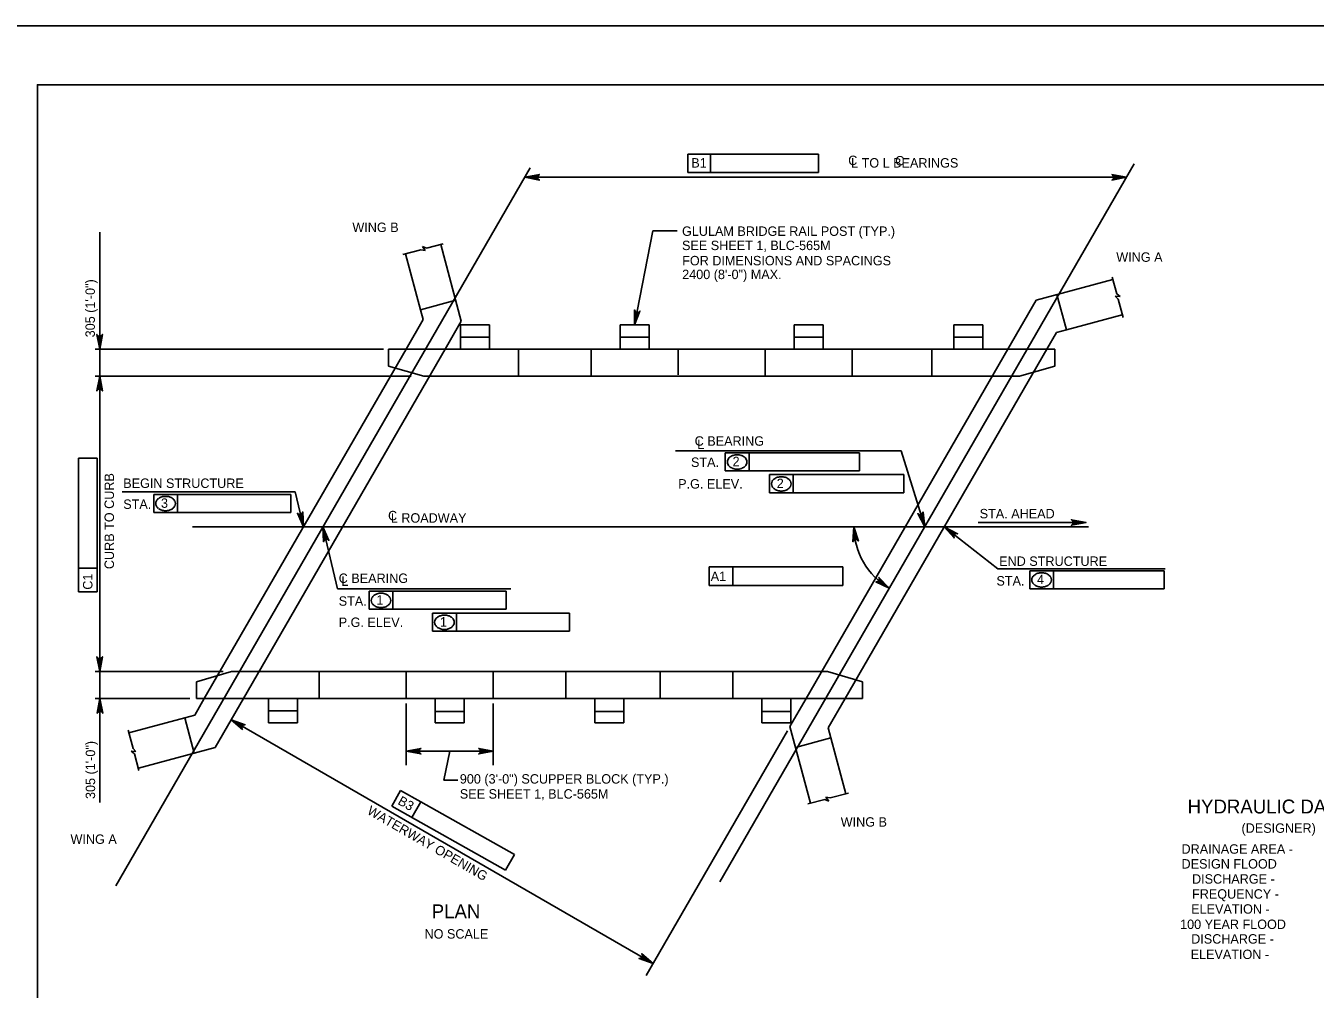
# Model space of a CAD drawing. Extents: x -8 to 75, y -110 to 0.
# Drawn here: x 1.6 to 18.01, y -12.26 to 0 of the extents above; entities that cross this region are included whole.
import ezdxf

# ---------------------------------------------------------------- set-up
doc = ezdxf.new("R2010")
doc.units = 0
for name, color, linetype in [('1', 7, 'Continuous'), ('2', 7, 'Continuous'), ('3', 7, 'Continuous'), ('4', 7, 'Continuous'), ('63', 7, 'Continuous')]:
    doc.layers.add(name, color=color, linetype=linetype)

msp = doc.modelspace()

# ---------------------------------------------------------------- linework, layer by layer
at = {"layer": '1'}
msp.add_lwpolyline([(1.75, -21.25), (33.25, -21.25), (33.25, -0.75), (1.75, -0.75)], close=True, dxfattribs=at)
at = {"layer": '2'}
for p, q in [((7.144, -3.757), (6.882, -2.781)), ((6.623, -3.613), (6.432, -2.902)), ((14.457, -3.491), (15.433, -3.229)), ((14.842, -3.869), (14.721, -3.42)), ((6.623, -3.613), (7.073, -3.493)), ((14.457, -3.491), (14.097, -4.113)), ((6.441, -4.113), (6.657, -3.739)), ((6.657, -3.739), (6.623, -3.613)), ((7.144, -3.757), (6.938, -4.113)), ((14.842, -3.869), (15.553, -3.679)), ((7.502, -3.806), (7.133, -3.806)), ((7.133, -3.806), (7.133, -4.113)), ((7.502, -3.806), (7.502, -4.113)), ((9.532, -3.806), (9.163, -3.806)), ((9.163, -3.806), (9.163, -4.113)), ((9.532, -3.806), (9.532, -4.113)), ((11.379, -3.806), (11.748, -3.806)), ((11.379, -3.806), (11.379, -4.113)), ((11.748, -3.806), (11.748, -4.113)), ((13.409, -3.806), (13.778, -3.806)), ((13.409, -3.806), (13.409, -4.113)), ((13.778, -3.806), (13.778, -4.113)), ((14.594, -4.113), (14.716, -3.903)), ((14.716, -3.903), (14.842, -3.869)), ((3.873, -8.56), (6.441, -4.113)), ((4.371, -8.56), (6.938, -4.113)), ((6.218, -4.113), (14.693, -4.113)), ((6.218, -4.329), (6.218, -4.113)), ((11.53, -8.56), (14.097, -4.113)), ((12.027, -8.56), (14.594, -4.113)), ((14.693, -4.329), (14.693, -4.113)), ((6.665, -4.459), (6.218, -4.329)), ((14.246, -4.459), (14.693, -4.329)), ((14.246, -4.459), (6.665, -4.459)), ((4.222, -8.214), (3.775, -8.345)), ((3.775, -8.345), (3.775, -8.56)), ((11.803, -8.214), (4.222, -8.214)), ((11.803, -8.214), (12.25, -8.345)), ((12.25, -8.345), (12.25, -8.56)), ((3.752, -8.771), (3.873, -8.56)), ((3.775, -8.56), (12.25, -8.56)), ((4.371, -8.56), (4.011, -9.183)), ((4.69, -8.868), (4.69, -8.56)), ((5.059, -8.868), (5.059, -8.56)), ((6.812, -8.868), (6.812, -8.56)), ((7.181, -8.868), (7.181, -8.56)), ((8.843, -8.868), (8.843, -8.56)), ((9.212, -8.868), (9.212, -8.56)), ((10.966, -8.868), (10.966, -8.56)), ((11.324, -8.916), (11.53, -8.56)), ((11.335, -8.868), (11.335, -8.56)), ((11.811, -8.934), (12.027, -8.56)), ((3.626, -8.804), (2.914, -8.995)), ((3.752, -8.771), (3.626, -8.804)), ((3.626, -8.804), (3.746, -9.254)), ((7.181, -8.725), (6.812, -8.725)), ((8.843, -8.725), (9.212, -8.725)), ((10.966, -8.725), (11.335, -8.725)), ((5.059, -8.868), (4.69, -8.868)), ((7.181, -8.868), (6.812, -8.868)), ((8.843, -8.868), (9.212, -8.868)), ((10.966, -8.868), (11.335, -8.868)), ((11.324, -8.916), (11.586, -9.893)), ((11.811, -8.934), (11.845, -9.06)), ((4.011, -9.183), (3.035, -9.445)), ((11.845, -9.06), (11.395, -9.181)), ((11.845, -9.06), (12.035, -9.772))]:
    msp.add_line(p, q, dxfattribs=at)
at = {"layer": '3'}
for p, q in [((10.433, -10.89), (15.706, -1.757)), ((2.747, -10.942), (8.02, -1.808)), ((6.7, -2.83), (6.914, -2.773)), ((6.398, -2.911), (6.631, -2.849)), ((6.684, -2.86), (6.631, -2.849)), ((6.65, -2.808), (6.684, -2.86)), ((6.7, -2.83), (6.65, -2.808)), ((15.482, -3.411), (15.424, -3.197)), ((15.463, -3.44), (15.5, -3.48)), ((15.525, -3.443), (15.463, -3.44)), ((15.482, -3.411), (15.525, -3.443)), ((15.563, -3.713), (15.5, -3.48)), ((7.502, -3.96), (7.133, -3.96)), ((9.532, -3.96), (9.163, -3.96)), ((11.379, -3.96), (11.748, -3.96)), ((13.409, -3.96), (13.778, -3.96)), ((7.871, -4.459), (7.871, -4.113)), ((8.794, -4.459), (8.794, -4.113)), ((9.902, -4.113), (9.902, -4.443)), ((11.009, -4.113), (11.009, -4.459)), ((12.117, -4.113), (12.117, -4.459)), ((13.132, -4.113), (13.132, -4.459)), ((5.335, -8.214), (5.335, -8.56)), ((6.443, -8.214), (6.443, -8.56)), ((7.551, -8.214), (7.551, -8.56)), ((8.474, -8.214), (8.474, -8.56)), ((9.674, -8.214), (9.674, -8.56)), ((10.597, -8.214), (10.597, -8.56)), ((5.059, -8.714), (4.69, -8.714)), ((2.905, -8.96), (2.968, -9.194)), ((2.986, -9.263), (2.942, -9.23)), ((2.942, -9.23), (3.005, -9.234)), ((3.005, -9.234), (2.968, -9.194)), ((2.986, -9.263), (3.043, -9.476)), ((11.818, -9.865), (11.783, -9.813)), ((11.783, -9.813), (11.837, -9.825)), ((12.07, -9.763), (11.837, -9.825)), ((11.767, -9.844), (11.554, -9.901)), ((11.767, -9.844), (11.818, -9.865))]:
    msp.add_line(p, q, dxfattribs=at)
at = {"layer": '4'}
for p, q in [((10.027, -1.634), (10.316, -1.634)), ((10.027, -1.865), (10.027, -1.634)), ((10.316, -1.865), (10.316, -1.634)), ((10.316, -1.634), (11.688, -1.634)), ((11.688, -1.634), (11.688, -1.865)), ((7.951, -1.928), (15.607, -1.928)), ((11.688, -1.865), (10.027, -1.865)), ((9.347, -3.806), (9.581, -2.611)), ((9.581, -2.611), (9.89, -2.611)), ((2.543, -2.627), (2.543, -9.884)), ((6.155, -4.113), (2.485, -4.113)), ((6.504, -4.459), (2.485, -4.459)), ((12.741, -5.408), (9.869, -5.408)), ((13.04, -6.375), (12.741, -5.408)), ((2.51, -5.501), (2.273, -5.5)), ((2.273, -6.899), (2.273, -5.5)), ((2.51, -7.201), (2.51, -5.501)), ((10.502, -5.433), (10.805, -5.433)), ((10.502, -5.663), (10.502, -5.433)), ((10.805, -5.663), (10.805, -5.433)), ((10.805, -5.433), (12.212, -5.433)), ((12.212, -5.433), (12.212, -5.663)), ((10.502, -5.663), (12.212, -5.663)), ((11.064, -5.711), (11.367, -5.711)), ((11.064, -5.942), (11.064, -5.711)), ((11.367, -5.942), (11.367, -5.711)), ((11.367, -5.711), (12.774, -5.711)), ((12.774, -5.711), (12.774, -5.942)), ((2.828, -5.931), (5.031, -5.931)), ((3.23, -6.192), (3.23, -5.962)), ((3.23, -5.962), (3.533, -5.962)), ((3.533, -6.192), (3.533, -5.962)), ((3.533, -5.962), (4.973, -5.962)), ((4.973, -5.962), (4.973, -6.192)), ((5.135, -6.375), (5.031, -5.931)), ((11.064, -5.942), (12.774, -5.942)), ((3.23, -6.192), (4.973, -6.192)), ((3.723, -6.375), (15.124, -6.375)), ((5.384, -6.375), (5.569, -7.163)), ((13.289, -6.375), (13.971, -6.909)), ((15.093, -6.319), (13.719, -6.319)), ((10.297, -6.886), (10.599, -6.886)), ((10.297, -6.886), (10.297, -7.122)), ((10.599, -7.122), (10.599, -6.886)), ((10.599, -6.886), (11.998, -6.886)), ((11.998, -7.122), (11.998, -6.886)), ((2.273, -7.201), (2.273, -6.899)), ((2.51, -6.899), (2.273, -6.899)), ((13.971, -6.909), (16.099, -6.909)), ((14.375, -6.933), (14.678, -6.933)), ((14.375, -7.164), (14.375, -6.933)), ((14.678, -7.164), (14.678, -6.933)), ((14.678, -6.933), (16.086, -6.933)), ((16.086, -6.933), (16.086, -7.164)), ((2.273, -7.201), (2.51, -7.201)), ((7.772, -7.163), (5.569, -7.163)), ((5.971, -7.194), (6.274, -7.194)), ((5.971, -7.424), (5.971, -7.194)), ((6.274, -7.424), (6.274, -7.194)), ((6.274, -7.194), (7.714, -7.194)), ((7.714, -7.194), (7.714, -7.424)), ((10.297, -7.122), (11.998, -7.122)), ((14.375, -7.164), (16.086, -7.164)), ((5.971, -7.424), (7.714, -7.424)), ((6.778, -7.703), (6.778, -7.472)), ((6.778, -7.472), (7.081, -7.472)), ((7.081, -7.703), (7.081, -7.472)), ((7.081, -7.472), (8.522, -7.472)), ((8.522, -7.472), (8.522, -7.703)), ((6.778, -7.703), (8.522, -7.703)), ((4.112, -8.214), (2.485, -8.214)), ((3.689, -8.56), (2.485, -8.56)), ((6.443, -8.622), (6.443, -9.407)), ((7.551, -8.622), (7.551, -9.407)), ((4.215, -8.83), (9.584, -11.93)), ((11.293, -8.97), (9.496, -12.083)), ((6.443, -9.23), (7.551, -9.23)), ((6.997, -9.23), (6.923, -9.599)), ((6.923, -9.599), (7.1, -9.599)), ((6.259, -9.93), (6.372, -9.729)), ((6.372, -9.729), (6.628, -9.873)), ((7.707, -10.744), (6.259, -9.93)), ((6.515, -10.074), (6.628, -9.873)), ((6.628, -9.873), (7.82, -10.543)), ((7.82, -10.543), (7.707, -10.744))]:
    msp.add_line(p, q, dxfattribs=at)
for points in [[(7.951, -1.928), (8.137, -1.893), (8.123, -1.903), (8.116, -1.916), (8.113, -1.928), (8.116, -1.941), (8.123, -1.953), (8.137, -1.963), (7.951, -1.928), (8.123, -1.953), (8.116, -1.941), (7.951, -1.928), (8.113, -1.928), (8.116, -1.916), (7.951, -1.928), (8.123, -1.903)], [(15.607, -1.928), (15.421, -1.963), (15.435, -1.953), (15.443, -1.941), (15.445, -1.928), (15.443, -1.916), (15.435, -1.903), (15.421, -1.893), (15.607, -1.928), (15.435, -1.903), (15.443, -1.916), (15.607, -1.928), (15.445, -1.928), (15.443, -1.941), (15.607, -1.928), (15.435, -1.953)], [(9.347, -3.806), (9.349, -3.616), (9.356, -3.632), (9.367, -3.642), (9.378, -3.646), (9.391, -3.647), (9.405, -3.642), (9.417, -3.629), (9.347, -3.806), (9.405, -3.642), (9.391, -3.647), (9.347, -3.806), (9.378, -3.646), (9.367, -3.642), (9.347, -3.806), (9.356, -3.632)], [(2.543, -4.113), (2.508, -3.927), (2.518, -3.941), (2.53, -3.949), (2.543, -3.951), (2.555, -3.949), (2.568, -3.941), (2.578, -3.927), (2.543, -4.113), (2.568, -3.941), (2.555, -3.949), (2.543, -4.113), (2.543, -3.951), (2.53, -3.949), (2.543, -4.113), (2.518, -3.941)], [(2.543, -4.459), (2.578, -4.646), (2.568, -4.631), (2.555, -4.624), (2.543, -4.622), (2.53, -4.624), (2.518, -4.631), (2.508, -4.646), (2.543, -4.459), (2.518, -4.631), (2.53, -4.624), (2.543, -4.459), (2.543, -4.622), (2.555, -4.624), (2.543, -4.459), (2.568, -4.631)], [(5.135, -6.375), (5.058, -6.202), (5.071, -6.213), (5.085, -6.218), (5.098, -6.217), (5.11, -6.212), (5.12, -6.202), (5.127, -6.186), (5.135, -6.375), (5.12, -6.202), (5.11, -6.212), (5.135, -6.375), (5.098, -6.217), (5.085, -6.218), (5.135, -6.375), (5.071, -6.213)], [(13.04, -6.375), (12.952, -6.207), (12.965, -6.218), (12.979, -6.221), (12.992, -6.22), (13.003, -6.214), (13.013, -6.203), (13.018, -6.187), (13.04, -6.375), (13.013, -6.203), (13.003, -6.214), (13.04, -6.375), (12.992, -6.22), (12.979, -6.221), (13.04, -6.375), (12.965, -6.218)], [(5.384, -6.375), (5.46, -6.548), (5.447, -6.537), (5.433, -6.532), (5.421, -6.533), (5.409, -6.538), (5.399, -6.548), (5.392, -6.564), (5.384, -6.375), (5.399, -6.548), (5.409, -6.538), (5.384, -6.375), (5.421, -6.533), (5.433, -6.532), (5.384, -6.375), (5.447, -6.537)], [(12.139, -6.375), (12.196, -6.556), (12.184, -6.543), (12.171, -6.537), (12.158, -6.536), (12.146, -6.54), (12.135, -6.549), (12.126, -6.564), (12.139, -6.375), (12.135, -6.549), (12.146, -6.54), (12.139, -6.375), (12.158, -6.536), (12.171, -6.537), (12.139, -6.375), (12.184, -6.543)], [(13.289, -6.375), (13.457, -6.462), (13.44, -6.461), (13.426, -6.466), (13.417, -6.475), (13.411, -6.486), (13.409, -6.501), (13.414, -6.517), (13.289, -6.375), (13.409, -6.501), (13.411, -6.486), (13.289, -6.375), (13.417, -6.475), (13.426, -6.466), (13.289, -6.375), (13.44, -6.461)], [(15.093, -6.319), (14.907, -6.354), (14.921, -6.344), (14.929, -6.331), (14.931, -6.319), (14.929, -6.306), (14.921, -6.294), (14.907, -6.284), (15.093, -6.319), (14.921, -6.294), (14.929, -6.306), (15.093, -6.319), (14.931, -6.319), (14.929, -6.331), (15.093, -6.319), (14.921, -6.344)], [(12.589, -7.156), (12.418, -7.075), (12.435, -7.075), (12.448, -7.07), (12.457, -7.061), (12.463, -7.049), (12.464, -7.035), (12.458, -7.018), (12.589, -7.156), (12.464, -7.035), (12.463, -7.049), (12.589, -7.156), (12.457, -7.061), (12.448, -7.07), (12.589, -7.156), (12.435, -7.075)], [(2.543, -8.214), (2.508, -8.028), (2.518, -8.042), (2.53, -8.05), (2.543, -8.052), (2.555, -8.05), (2.568, -8.042), (2.578, -8.028), (2.543, -8.214), (2.568, -8.042), (2.555, -8.05), (2.543, -8.214), (2.543, -8.052), (2.53, -8.05), (2.543, -8.214), (2.518, -8.042)], [(2.547, -8.561), (2.582, -8.747), (2.572, -8.733), (2.56, -8.726), (2.547, -8.723), (2.535, -8.726), (2.522, -8.733), (2.512, -8.747), (2.547, -8.561), (2.522, -8.733), (2.535, -8.726), (2.547, -8.561), (2.547, -8.723), (2.56, -8.726), (2.547, -8.561), (2.572, -8.733)], [(4.215, -8.83), (4.394, -8.893), (4.377, -8.894), (4.364, -8.901), (4.356, -8.911), (4.351, -8.923), (4.352, -8.937), (4.359, -8.953), (4.215, -8.83), (4.352, -8.937), (4.351, -8.923), (4.215, -8.83), (4.356, -8.911), (4.364, -8.901), (4.215, -8.83), (4.377, -8.894)], [(6.443, -9.23), (6.629, -9.195), (6.615, -9.205), (6.607, -9.218), (6.605, -9.23), (6.607, -9.243), (6.615, -9.255), (6.629, -9.265), (6.443, -9.23), (6.615, -9.255), (6.607, -9.243), (6.443, -9.23), (6.605, -9.23), (6.607, -9.218), (6.443, -9.23), (6.615, -9.205)], [(7.551, -9.23), (7.365, -9.265), (7.379, -9.255), (7.386, -9.243), (7.388, -9.23), (7.386, -9.218), (7.379, -9.205), (7.365, -9.195), (7.551, -9.23), (7.379, -9.205), (7.386, -9.218), (7.551, -9.23), (7.388, -9.23), (7.386, -9.243), (7.551, -9.23), (7.379, -9.255)], [(9.584, -11.93), (9.405, -11.867), (9.423, -11.865), (9.435, -11.858), (9.444, -11.848), (9.448, -11.837), (9.448, -11.822), (9.44, -11.806), (9.584, -11.93), (9.448, -11.822), (9.448, -11.837), (9.584, -11.93), (9.444, -11.848), (9.435, -11.858), (9.584, -11.93), (9.423, -11.865)]]:
    msp.add_lwpolyline(points, dxfattribs=at)
for points in [[(2.524, -3.998), (2.562, -3.998), (2.543, -4.113)], [(2.524, -4.575), (2.562, -4.575), (2.543, -4.459)], [(5.391, -6.494), (5.43, -6.486), (5.384, -6.375)], [(13.024, -6.256), (12.986, -6.268), (13.04, -6.375)], [(2.524, -8.099), (2.562, -8.099), (2.543, -8.214)], [(2.524, -8.676), (2.562, -8.676), (2.543, -8.56)], [(6.561, -9.21), (6.561, -9.25), (6.443, -9.23)], [(7.433, -9.21), (7.433, -9.25), (7.551, -9.23)], [(9.492, -11.854), (9.472, -11.888), (9.584, -11.93)]]:
    msp.add_lwpolyline(points, close=True, dxfattribs=at)
for centre, radius, start, end in [((10.597, -5.55), 0.0684, 150.6308, 180), ((10.597, -5.55), 0.0684, 180, 209.3692), ((10.624, -5.565), 0.0995, 126.3544, 150.6308), ((10.642, -5.589), 0.129, 106.9552, 126.3544), ((10.653, -5.627), 0.169, 90, 106.9552), ((10.653, -5.627), 0.169, 73.0448, 90), ((10.665, -5.589), 0.129, 53.6456, 73.0448), ((10.683, -5.565), 0.0995, 29.3692, 53.6456), ((10.71, -5.55), 0.0684, 0, 29.3692), ((10.71, -5.55), 0.0684, 330.6308, 0), ((10.624, -5.535), 0.0995, 209.3692, 233.6456), ((10.642, -5.511), 0.129, 233.6456, 253.0448), ((10.653, -5.473), 0.169, 253.0448, 270), ((10.653, -5.473), 0.169, 270, 286.9552), ((10.665, -5.511), 0.129, 286.9552, 306.3544), ((10.683, -5.535), 0.0995, 306.3544, 330.6308), ((11.215, -5.906), 0.169, 90, 106.9552), ((11.215, -5.906), 0.169, 73.0448, 90), ((11.159, -5.828), 0.0684, 150.6308, 180), ((11.159, -5.828), 0.0684, 180, 209.3692), ((11.186, -5.844), 0.0995, 126.3544, 150.6308), ((11.186, -5.813), 0.0995, 209.3692, 233.6456), ((11.203, -5.868), 0.129, 106.9552, 126.3544), ((11.203, -5.789), 0.129, 233.6456, 253.0448), ((11.227, -5.868), 0.129, 53.6456, 73.0448), ((11.227, -5.789), 0.129, 286.9552, 306.3544), ((11.244, -5.844), 0.0995, 29.3692, 53.6456), ((11.244, -5.813), 0.0995, 306.3544, 330.6308), ((11.271, -5.828), 0.0684, 0, 29.3692), ((11.271, -5.828), 0.0684, 330.6308, 0), ((3.325, -6.079), 0.0684, 150.6308, 180), ((3.352, -6.094), 0.0995, 126.3544, 150.6308), ((3.37, -6.118), 0.129, 106.9552, 126.3544), ((3.381, -6.156), 0.169, 90, 106.9552), ((3.381, -6.156), 0.169, 73.0448, 90), ((3.393, -6.118), 0.129, 53.6456, 73.0448), ((3.41, -6.094), 0.0995, 29.3692, 53.6456), ((3.438, -6.079), 0.0684, 0, 29.3692), ((11.215, -5.751), 0.169, 253.0448, 270), ((11.215, -5.751), 0.169, 270, 286.9552), ((3.325, -6.079), 0.0684, 180, 209.3692), ((3.352, -6.063), 0.0995, 209.3692, 233.6456), ((3.37, -6.04), 0.129, 233.6456, 253.0448), ((3.381, -6.002), 0.169, 253.0448, 270), ((3.381, -6.002), 0.169, 270, 286.9552), ((3.393, -6.04), 0.129, 286.9552, 306.3544), ((3.41, -6.063), 0.0995, 306.3544, 330.6308), ((3.438, -6.079), 0.0684, 330.6308, 0), ((13.04, -6.375), 0.901, 179.9993, 239.9995), ((14.47, -7.05), 0.0684, 150.6308, 180), ((14.47, -7.05), 0.0684, 180, 209.3692), ((14.498, -7.066), 0.0995, 126.3544, 150.6308), ((14.515, -7.09), 0.129, 106.9552, 126.3544), ((14.527, -7.128), 0.169, 90, 106.9552), ((14.527, -7.128), 0.169, 73.0448, 90), ((14.538, -7.09), 0.129, 53.6456, 73.0448), ((14.556, -7.066), 0.0995, 29.3692, 53.6456), ((14.583, -7.05), 0.0684, 0, 29.3692), ((14.583, -7.05), 0.0684, 330.6308, 0), ((14.498, -7.035), 0.0995, 209.3692, 233.6456), ((14.515, -7.011), 0.129, 233.6456, 253.0448), ((14.527, -6.973), 0.169, 253.0448, 270), ((14.527, -6.973), 0.169, 270, 286.9552), ((14.538, -7.011), 0.129, 286.9552, 306.3544), ((14.556, -7.035), 0.0995, 306.3544, 330.6308), ((6.066, -7.311), 0.0684, 150.6308, 180), ((6.066, -7.311), 0.0684, 180, 209.3692), ((6.093, -7.326), 0.0995, 126.3544, 150.6308), ((6.093, -7.296), 0.0995, 209.3692, 233.6456), ((6.111, -7.35), 0.129, 106.9552, 126.3544), ((6.111, -7.272), 0.129, 233.6456, 253.0448), ((6.122, -7.388), 0.169, 90, 106.9552), ((6.122, -7.388), 0.169, 73.0448, 90), ((6.134, -7.35), 0.129, 53.6456, 73.0448), ((6.134, -7.272), 0.129, 286.9552, 306.3544), ((6.151, -7.326), 0.0995, 29.3692, 53.6456), ((6.151, -7.296), 0.0995, 306.3544, 330.6308), ((6.178, -7.311), 0.0684, 0, 29.3692), ((6.178, -7.311), 0.0684, 330.6308, 0), ((6.122, -7.234), 0.169, 253.0448, 270), ((6.122, -7.234), 0.169, 270, 286.9552), ((6.9, -7.605), 0.0995, 126.3544, 150.6308), ((6.918, -7.629), 0.129, 106.9552, 126.3544), ((6.93, -7.667), 0.169, 90, 106.9552), ((6.93, -7.667), 0.169, 73.0448, 90), ((6.941, -7.629), 0.129, 53.6456, 73.0448), ((6.959, -7.605), 0.0995, 29.3692, 53.6456), ((6.873, -7.59), 0.0684, 150.6308, 180), ((6.873, -7.59), 0.0684, 180, 209.3692), ((6.9, -7.574), 0.0995, 209.3692, 233.6456), ((6.918, -7.55), 0.129, 233.6456, 253.0448), ((6.93, -7.513), 0.169, 253.0448, 270), ((6.93, -7.513), 0.169, 270, 286.9552), ((6.941, -7.55), 0.129, 286.9552, 306.3544), ((6.959, -7.574), 0.0995, 306.3544, 330.6308), ((6.986, -7.59), 0.0684, 0, 29.3692), ((6.986, -7.59), 0.0684, 330.6308, 0)]:
    msp.add_arc(centre, radius, start, end, dxfattribs=at)
at = {"layer": '63'}
msp.add_lwpolyline([(0, -22), (34, -22), (34, 0), (0, 0)], close=True, dxfattribs=at)

# ---------------------------------------------------------------- texts
at = {"layer": '4'}
for s, height, p in [('B1', 0.12, (10.07, -1.804)), ('C', 0.12, (12.066, -1.772)), ('L TO L BEARINGS', 0.12, (12.103, -1.804)), ('C', 0.12, (12.664, -1.777)), ('WING B', 0.12, (5.758, -2.624)), ('GLULAM BRIDGE RAIL POST (TYP.)', 0.12, (9.952, -2.673)), ('SEE SHEET 1, BLC-565M', 0.12, (9.952, -2.854)), ('FOR DIMENSIONS AND SPACINGS', 0.12, (9.954, -3.048)), ('WING A', 0.12, (15.477, -3.003)), ('2400 (8\'-0") MAX.', 0.12, (9.954, -3.223)), ('C BEARING', 0.12, (10.113, -5.343)), ('L', 0.12, (10.146, -5.386)), ('STA.', 0.12, (10.066, -5.613)), ('2', 0.12, (10.595, -5.604)), ('BEGIN STRUCTURE', 0.12, (2.843, -5.88)), ('P.G. ELEV.', 0.12, (9.903, -5.888)), ('2', 0.12, (11.157, -5.882)), ('STA.', 0.12, (2.843, -6.147)), ('3', 0.12, (3.323, -6.133)), ('C', 0.12, (6.212, -6.292)), ('L ROADWAY', 0.12, (6.247, -6.322)), ('STA. AHEAD', 0.12, (13.739, -6.267)), ('END STRUCTURE', 0.12, (13.987, -6.872)), ('C BEARING', 0.12, (5.584, -7.089)), ('L', 0.12, (5.617, -7.126)), ('STA.', 0.12, (13.952, -7.122)), ('4', 0.12, (14.469, -7.104)), ('STA.', 0.12, (5.584, -7.379)), ('1', 0.12, (6.064, -7.365)), ('P.G. ELEV.', 0.12, (5.584, -7.649)), ('1', 0.12, (6.872, -7.644)), ('900 (3\'-0") SCUPPER BLOCK (TYP.)', 0.12, (7.125, -9.642)), ('SEE SHEET 1, BLC-565M', 0.12, (7.125, -9.833)), ('HYDRAULIC DATA', 0.17717, (16.384, -10.022)), ('WING B', 0.12, (11.971, -10.19)), ('(DESIGNER)', 0.12, (17.07, -10.268)), ('WING A', 0.12, (2.172, -10.409)), ('DRAINAGE AREA - ', 0.12, (16.307, -10.534)), ('DESIGN FLOOD  ', 0.12, (16.307, -10.723)), ('   DISCHARGE - ', 0.12, (16.307, -10.915)), ('   FREQUENCY - ', 0.12, (16.307, -11.106)), ('PLAN', 0.1772, (6.767, -11.356)), ('   ELEVATION - ', 0.12, (16.296, -11.297)), ('100 YEAR FLOOD', 0.12, (16.289, -11.492)), ('NO SCALE', 0.12, (6.676, -11.614)), ('   DISCHARGE - ', 0.12, (16.296, -11.678)), ('   ELEVATION - ', 0.12, (16.289, -11.874))]:
    msp.add_text(s, height=height, dxfattribs=at).set_placement(p)
for s, rotation, p in [('305 (1\'-0")', 90, (2.482, -3.964)), ('CURB TO CURB', 90, (2.725, -6.913)), ('C1', 89.9382, (2.451, -7.175)), ('A1', 359.9382, (10.317, -7.064)), ('305 (1\'-0")', 90, (2.485, -9.838)), ('B3', 330.6611, (6.326, -9.898)), ('WATERWAY OPENING', 330, (5.936, -10.021))]:
    msp.add_text(s, height=0.12, rotation=rotation, dxfattribs=at).set_placement(p)

doc.saveas('drawing.dxf')
